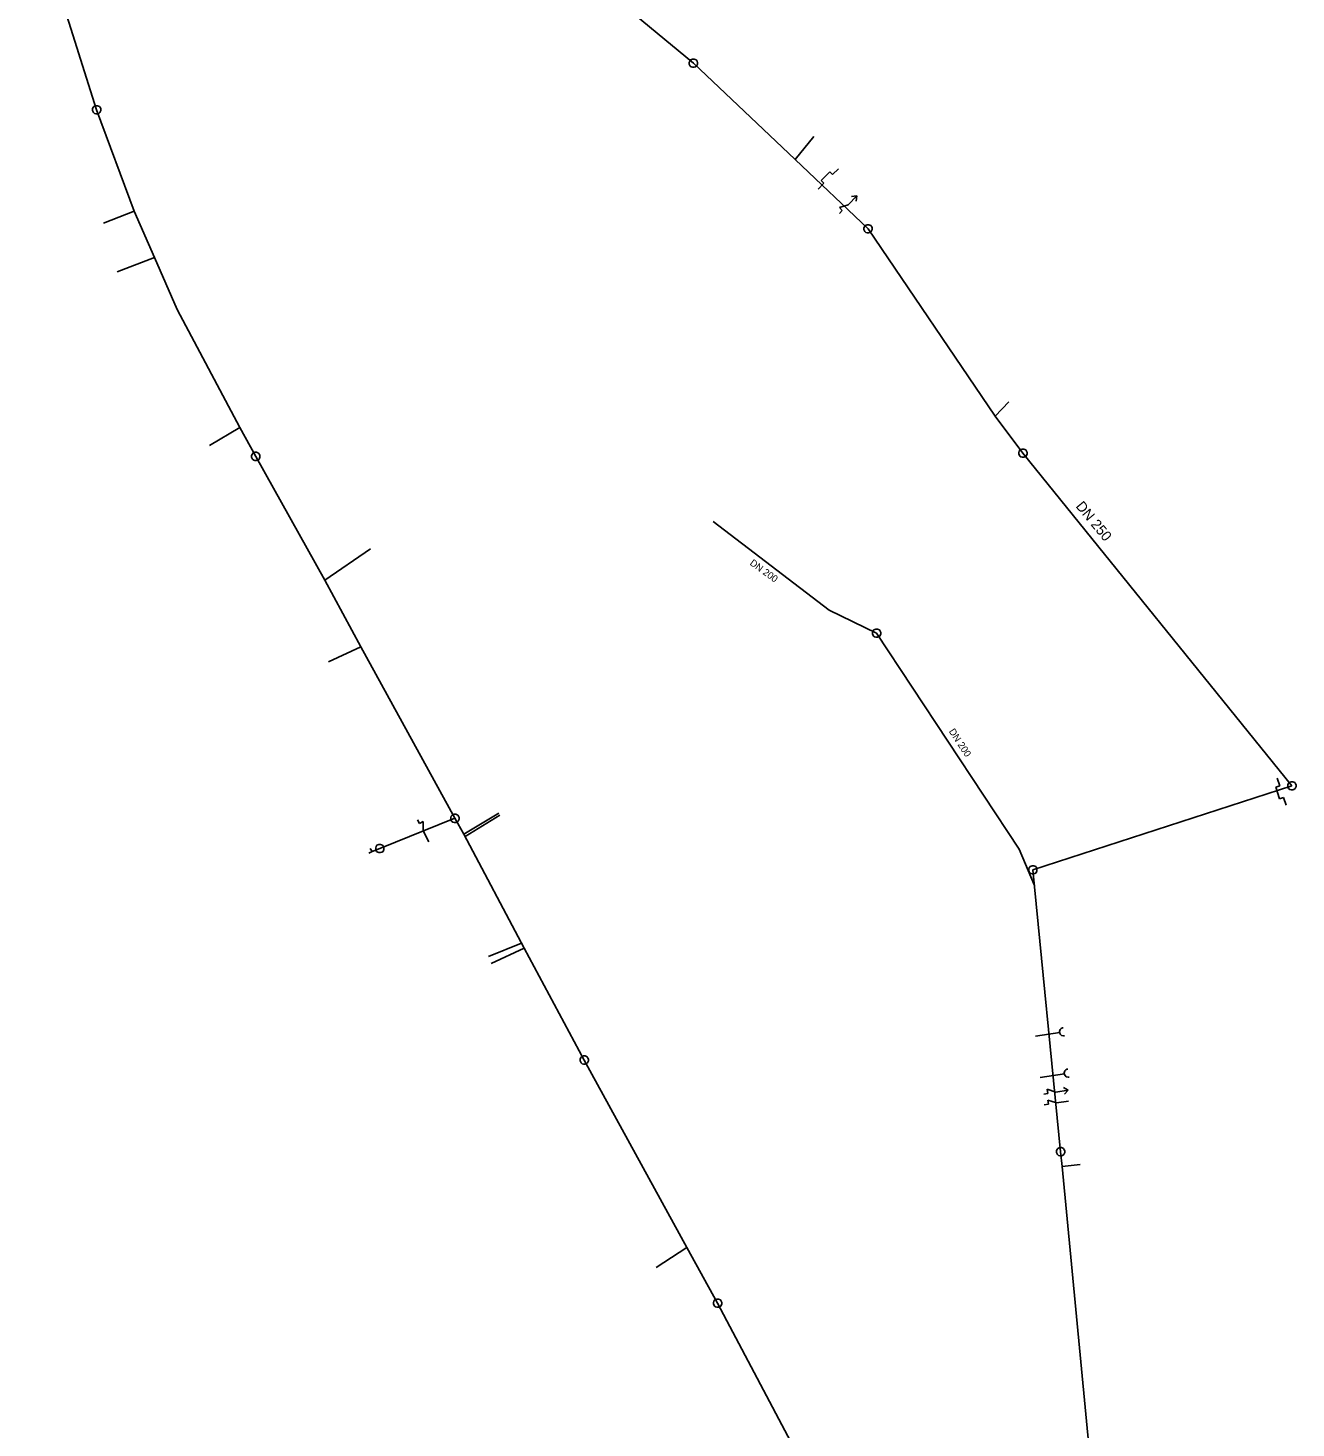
# Model space of a CAD drawing. Extents: x -717256 to -716843, y -1145423 to -1142840.
# Drawn here: x -717124.6 to -716969.5, y -1144562.5 to -1144391.3 of the extents above; entities that cross this region are included whole.
import ezdxf

# ---------------------------------------------------------------- set-up
doc = ezdxf.new("R2010")
doc.units = 0
for name, color, linetype in [('Vrstva 30', 7, 'Continuous'), ('Vrstva 31', 7, 'Continuous'), ('Vrstva 9', 7, 'Continuous')]:
    doc.layers.add(name, color=color, linetype=linetype)

msp = doc.modelspace()

# ---------------------------------------------------------------- linework, layer by layer
at = {"layer": 'Vrstva 30'}
for p, q in [((-717116.213, -1144401.308), (-717124.609, -1144374.682)), ((-717055.56, -1144385.37), (-717043.24, -1144395.61)), ((-717043.74, -1144395.51), (-717043.69, -1144395.36)), ((-717043.74, -1144395.71), (-717043.74, -1144395.51)), ((-717043.64, -1144395.96), (-717043.74, -1144395.71)), ((-717043.69, -1144395.36), (-717043.59, -1144395.21)), ((-717043.49, -1144396.06), (-717043.64, -1144395.96)), ((-717043.59, -1144395.21), (-717043.34, -1144395.11)), ((-717043.34, -1144396.11), (-717043.49, -1144396.06)), ((-717043.34, -1144395.11), (-717043.14, -1144395.11)), ((-717043.14, -1144396.11), (-717043.34, -1144396.11)), ((-717043.24, -1144395.61), (-717030.8, -1144407.402)), ((-717043.14, -1144395.11), (-717042.89, -1144395.21)), ((-717042.99, -1144396.06), (-717043.14, -1144396.11)), ((-717042.84, -1144395.96), (-717042.99, -1144396.06)), ((-717042.89, -1144395.21), (-717042.79, -1144395.36)), ((-717042.74, -1144395.71), (-717042.84, -1144395.96)), ((-717042.79, -1144395.36), (-717042.74, -1144395.51)), ((-717042.74, -1144395.51), (-717042.74, -1144395.71)), ((-717116.713, -1144401.208), (-717116.663, -1144401.058)), ((-717116.713, -1144401.408), (-717116.713, -1144401.208)), ((-717116.663, -1144401.058), (-717116.563, -1144400.908)), ((-717116.563, -1144400.908), (-717116.313, -1144400.808)), ((-717116.313, -1144400.808), (-717116.113, -1144400.808)), ((-717111.636, -1144413.702), (-717116.213, -1144401.308)), ((-717116.113, -1144400.808), (-717115.863, -1144400.908)), ((-717115.863, -1144400.908), (-717115.763, -1144401.058)), ((-717115.763, -1144401.058), (-717115.713, -1144401.208)), ((-717115.713, -1144401.208), (-717115.713, -1144401.408)), ((-717116.613, -1144401.658), (-717116.713, -1144401.408)), ((-717116.463, -1144401.758), (-717116.613, -1144401.658)), ((-717116.313, -1144401.808), (-717116.463, -1144401.758)), ((-717116.113, -1144401.808), (-717116.313, -1144401.808)), ((-717115.963, -1144401.758), (-717116.113, -1144401.808)), ((-717115.813, -1144401.658), (-717115.963, -1144401.758)), ((-717115.713, -1144401.408), (-717115.813, -1144401.658)), ((-717030.8, -1144407.402), (-717021.88, -1144415.86)), ((-717109.14, -1144419.386), (-717111.636, -1144413.702)), ((-717022.38, -1144415.76), (-717022.33, -1144415.61)), ((-717022.38, -1144415.96), (-717022.38, -1144415.76)), ((-717022.28, -1144416.21), (-717022.38, -1144415.96)), ((-717022.33, -1144415.61), (-717022.23, -1144415.46)), ((-717022.13, -1144416.31), (-717022.28, -1144416.21)), ((-717022.23, -1144415.46), (-717021.98, -1144415.36)), ((-717021.98, -1144416.36), (-717022.13, -1144416.31)), ((-717021.98, -1144415.36), (-717021.78, -1144415.36)), ((-717021.78, -1144416.36), (-717021.98, -1144416.36)), ((-717021.88, -1144415.86), (-717006.35, -1144438.77)), ((-717021.78, -1144415.36), (-717021.53, -1144415.46)), ((-717021.63, -1144416.31), (-717021.78, -1144416.36)), ((-717021.48, -1144416.21), (-717021.63, -1144416.31)), ((-717021.53, -1144415.46), (-717021.43, -1144415.61)), ((-717021.38, -1144415.96), (-717021.48, -1144416.21)), ((-717021.43, -1144415.61), (-717021.38, -1144415.76)), ((-717021.38, -1144415.76), (-717021.38, -1144415.96)), ((-717106.347, -1144425.727), (-717109.14, -1144419.386)), ((-717098.715, -1144440.159), (-717106.347, -1144425.727)), ((-717006.35, -1144438.77), (-717002.935, -1144443.298)), ((-717096.757, -1144443.693), (-717098.715, -1144440.159)), ((-717097.257, -1144443.593), (-717097.207, -1144443.443)), ((-717097.257, -1144443.793), (-717097.257, -1144443.593)), ((-717097.157, -1144444.043), (-717097.257, -1144443.793)), ((-717097.207, -1144443.443), (-717097.107, -1144443.293)), ((-717097.007, -1144444.143), (-717097.157, -1144444.043)), ((-717097.107, -1144443.293), (-717096.857, -1144443.193)), ((-717096.857, -1144443.193), (-717096.657, -1144443.193)), ((-717088.292, -1144458.816), (-717096.757, -1144443.693)), ((-717096.657, -1144443.193), (-717096.407, -1144443.293)), ((-717096.357, -1144444.043), (-717096.507, -1144444.143)), ((-717096.407, -1144443.293), (-717096.307, -1144443.443)), ((-717096.257, -1144443.793), (-717096.357, -1144444.043)), ((-717096.307, -1144443.443), (-717096.257, -1144443.593)), ((-717096.257, -1144443.593), (-717096.257, -1144443.793)), ((-717003.435, -1144443.198), (-717003.385, -1144443.048)), ((-717003.435, -1144443.398), (-717003.435, -1144443.198)), ((-717003.335, -1144443.648), (-717003.435, -1144443.398)), ((-717003.385, -1144443.048), (-717003.285, -1144442.898)), ((-717003.185, -1144443.748), (-717003.335, -1144443.648)), ((-717003.285, -1144442.898), (-717003.035, -1144442.798)), ((-717003.035, -1144443.798), (-717003.185, -1144443.748)), ((-717003.035, -1144442.798), (-717002.835, -1144442.798)), ((-717002.835, -1144443.798), (-717003.035, -1144443.798)), ((-717002.935, -1144443.298), (-716970.042, -1144483.973)), ((-717002.835, -1144442.798), (-717002.585, -1144442.898)), ((-717002.685, -1144443.748), (-717002.835, -1144443.798)), ((-717002.535, -1144443.648), (-717002.685, -1144443.748)), ((-717002.585, -1144442.898), (-717002.485, -1144443.048)), ((-717002.435, -1144443.398), (-717002.535, -1144443.648)), ((-717002.485, -1144443.048), (-717002.435, -1144443.198)), ((-717002.435, -1144443.198), (-717002.435, -1144443.398)), ((-717096.857, -1144444.193), (-717097.007, -1144444.143)), ((-717096.657, -1144444.193), (-717096.857, -1144444.193)), ((-717096.507, -1144444.143), (-717096.657, -1144444.193)), ((-717083.895, -1144466.986), (-717088.292, -1144458.816)), ((-717021.33, -1144465.21), (-717021.28, -1144465.06)), ((-717021.33, -1144465.41), (-717021.33, -1144465.21)), ((-717021.23, -1144465.66), (-717021.33, -1144465.41)), ((-717021.28, -1144465.06), (-717021.18, -1144464.91)), ((-717021.08, -1144465.76), (-717021.23, -1144465.66)), ((-717021.18, -1144464.91), (-717020.93, -1144464.81)), ((-717020.93, -1144465.81), (-717021.08, -1144465.76)), ((-717020.93, -1144464.81), (-717020.73, -1144464.81)), ((-717020.73, -1144465.81), (-717020.93, -1144465.81)), ((-717003.389, -1144491.727), (-717020.83, -1144465.31)), ((-717020.73, -1144464.81), (-717020.48, -1144464.91)), ((-717020.58, -1144465.76), (-717020.73, -1144465.81)), ((-717020.43, -1144465.66), (-717020.58, -1144465.76)), ((-717020.48, -1144464.91), (-717020.38, -1144465.06)), ((-717020.33, -1144465.41), (-717020.43, -1144465.66)), ((-717020.38, -1144465.06), (-717020.33, -1144465.21)), ((-717020.33, -1144465.21), (-717020.33, -1144465.41)), ((-717072.4, -1144487.954), (-717083.895, -1144466.986)), ((-716970.392, -1144483.573), (-716970.142, -1144483.473)), ((-716970.142, -1144483.473), (-716969.942, -1144483.473)), ((-716969.942, -1144483.473), (-716969.692, -1144483.573)), ((-717001.716, -1144494.256), (-716970.042, -1144483.973)), ((-716970.542, -1144483.873), (-716970.492, -1144483.723)), ((-716970.542, -1144484.073), (-716970.542, -1144483.873)), ((-716970.442, -1144484.323), (-716970.542, -1144484.073)), ((-716970.492, -1144483.723), (-716970.392, -1144483.573)), ((-716970.292, -1144484.423), (-716970.442, -1144484.323)), ((-716970.142, -1144484.473), (-716970.292, -1144484.423)), ((-716969.942, -1144484.473), (-716970.142, -1144484.473)), ((-716969.792, -1144484.423), (-716969.942, -1144484.473)), ((-716969.642, -1144484.323), (-716969.792, -1144484.423)), ((-716969.692, -1144483.573), (-716969.592, -1144483.723)), ((-716969.542, -1144484.073), (-716969.642, -1144484.323)), ((-716969.592, -1144483.723), (-716969.542, -1144483.873)), ((-716969.542, -1144483.873), (-716969.542, -1144484.073)), ((-717072.4, -1144487.954), (-717081.59, -1144491.65)), ((-717072.9, -1144487.854), (-717072.85, -1144487.704)), ((-717072.9, -1144488.054), (-717072.9, -1144487.854)), ((-717072.8, -1144488.304), (-717072.9, -1144488.054)), ((-717072.85, -1144487.704), (-717072.75, -1144487.554)), ((-717072.65, -1144488.404), (-717072.8, -1144488.304)), ((-717072.75, -1144487.554), (-717072.5, -1144487.454)), ((-717072.5, -1144488.454), (-717072.65, -1144488.404)), ((-717072.5, -1144487.454), (-717072.3, -1144487.454)), ((-717072.3, -1144488.454), (-717072.5, -1144488.454)), ((-717071.315, -1144489.899), (-717072.4, -1144487.954)), ((-717072.3, -1144487.454), (-717072.05, -1144487.554)), ((-717072.15, -1144488.404), (-717072.3, -1144488.454)), ((-717072, -1144488.304), (-717072.15, -1144488.404)), ((-717072.05, -1144487.554), (-717071.95, -1144487.704)), ((-717071.9, -1144488.054), (-717072, -1144488.304)), ((-717071.95, -1144487.704), (-717071.9, -1144487.854)), ((-717071.9, -1144487.854), (-717071.9, -1144488.054)), ((-717063.944, -1144503.812), (-717071.315, -1144489.899)), ((-717082.09, -1144491.55), (-717082.04, -1144491.4)), ((-717082.09, -1144491.75), (-717082.09, -1144491.55)), ((-717081.99, -1144492), (-717082.09, -1144491.75)), ((-717082.04, -1144491.4), (-717081.94, -1144491.25)), ((-717081.84, -1144492.1), (-717081.99, -1144492)), ((-717081.94, -1144491.25), (-717081.69, -1144491.15)), ((-717081.69, -1144491.15), (-717081.49, -1144491.15)), ((-717081.49, -1144491.15), (-717081.24, -1144491.25)), ((-717081.19, -1144492), (-717081.34, -1144492.1)), ((-717081.24, -1144491.25), (-717081.14, -1144491.4)), ((-717081.09, -1144491.75), (-717081.19, -1144492)), ((-717081.14, -1144491.4), (-717081.09, -1144491.55)), ((-717081.09, -1144491.55), (-717081.09, -1144491.75)), ((-717001.527, -1144496.17), (-717003.389, -1144491.727)), ((-717081.69, -1144492.15), (-717081.84, -1144492.1)), ((-717081.49, -1144492.15), (-717081.69, -1144492.15)), ((-717081.34, -1144492.1), (-717081.49, -1144492.15)), ((-717002.066, -1144493.856), (-717001.816, -1144493.756)), ((-717001.816, -1144493.756), (-717001.616, -1144493.756)), ((-717001.616, -1144493.756), (-717001.366, -1144493.856)), ((-717002.216, -1144494.156), (-717002.166, -1144494.006)), ((-717002.216, -1144494.356), (-717002.216, -1144494.156)), ((-717002.116, -1144494.606), (-717002.216, -1144494.356)), ((-717002.166, -1144494.006), (-717002.066, -1144493.856)), ((-717001.966, -1144494.706), (-717002.116, -1144494.606)), ((-717001.816, -1144494.756), (-717001.966, -1144494.706)), ((-717001.616, -1144494.756), (-717001.816, -1144494.756)), ((-717001.716, -1144494.256), (-716998.328, -1144528.729)), ((-717001.466, -1144494.706), (-717001.616, -1144494.756)), ((-717001.316, -1144494.606), (-717001.466, -1144494.706)), ((-717001.366, -1144493.856), (-717001.266, -1144494.006)), ((-717001.216, -1144494.356), (-717001.316, -1144494.606)), ((-717001.266, -1144494.006), (-717001.216, -1144494.156)), ((-717001.216, -1144494.156), (-717001.216, -1144494.356)), ((-717056.577, -1144517.515), (-717063.944, -1144503.812)), ((-717057.077, -1144517.415), (-717057.027, -1144517.265)), ((-717057.077, -1144517.615), (-717057.077, -1144517.415)), ((-717056.977, -1144517.865), (-717057.077, -1144517.615)), ((-717057.027, -1144517.265), (-717056.927, -1144517.115)), ((-717056.927, -1144517.115), (-717056.677, -1144517.015)), ((-717056.677, -1144517.015), (-717056.477, -1144517.015)), ((-717044.019, -1144540.452), (-717056.577, -1144517.515)), ((-717056.477, -1144517.015), (-717056.227, -1144517.115)), ((-717056.227, -1144517.115), (-717056.127, -1144517.265)), ((-717056.077, -1144517.615), (-717056.177, -1144517.865)), ((-717056.127, -1144517.265), (-717056.077, -1144517.415)), ((-717056.077, -1144517.415), (-717056.077, -1144517.615)), ((-717056.827, -1144517.965), (-717056.977, -1144517.865)), ((-717056.677, -1144518.015), (-717056.827, -1144517.965)), ((-717056.477, -1144518.015), (-717056.677, -1144518.015)), ((-717056.327, -1144517.965), (-717056.477, -1144518.015)), ((-717056.177, -1144517.865), (-717056.327, -1144517.965)), ((-716998.828, -1144528.629), (-716998.778, -1144528.479)), ((-716998.828, -1144528.829), (-716998.828, -1144528.629)), ((-716998.728, -1144529.079), (-716998.828, -1144528.829)), ((-716998.778, -1144528.479), (-716998.678, -1144528.329)), ((-716998.578, -1144529.179), (-716998.728, -1144529.079)), ((-716998.678, -1144528.329), (-716998.428, -1144528.229)), ((-716998.428, -1144529.229), (-716998.578, -1144529.179)), ((-716998.428, -1144528.229), (-716998.228, -1144528.229)), ((-716998.228, -1144529.229), (-716998.428, -1144529.229)), ((-716998.328, -1144528.729), (-716998.155, -1144530.526)), ((-716998.228, -1144528.229), (-716997.978, -1144528.329)), ((-716998.078, -1144529.179), (-716998.228, -1144529.229)), ((-716997.928, -1144529.079), (-716998.078, -1144529.179)), ((-716997.978, -1144528.329), (-716997.878, -1144528.479)), ((-716997.828, -1144528.829), (-716997.928, -1144529.079)), ((-716997.878, -1144528.479), (-716997.828, -1144528.629)), ((-716997.828, -1144528.629), (-716997.828, -1144528.829)), ((-716998.155, -1144530.526), (-716994.12, -1144572.47)), ((-717040.274, -1144547.245), (-717044.019, -1144540.452)), ((-717040.724, -1144546.995), (-717040.624, -1144546.845)), ((-717040.624, -1144546.845), (-717040.374, -1144546.745)), ((-717040.374, -1144546.745), (-717040.174, -1144546.745)), ((-717040.174, -1144546.745), (-717039.924, -1144546.845)), ((-717039.924, -1144546.845), (-717039.824, -1144546.995)), ((-717040.774, -1144547.145), (-717040.724, -1144546.995)), ((-717040.774, -1144547.345), (-717040.774, -1144547.145)), ((-717040.674, -1144547.595), (-717040.774, -1144547.345)), ((-717040.524, -1144547.695), (-717040.674, -1144547.595)), ((-717040.374, -1144547.745), (-717040.524, -1144547.695)), ((-717040.174, -1144547.745), (-717040.374, -1144547.745)), ((-717029.258, -1144568.056), (-717040.274, -1144547.245)), ((-717040.024, -1144547.695), (-717040.174, -1144547.745)), ((-717039.874, -1144547.595), (-717040.024, -1144547.695)), ((-717039.774, -1144547.345), (-717039.874, -1144547.595)), ((-717039.824, -1144546.995), (-717039.774, -1144547.145)), ((-717039.774, -1144547.145), (-717039.774, -1144547.345))]:
    msp.add_line(p, q, dxfattribs=at)
at = {"layer": 'Vrstva 31'}
for p, q in [((-717028.5, -1144404.56), (-717030.8, -1144407.402)), ((-717111.636, -1144413.702), (-717115.382, -1144415.153)), ((-717109.14, -1144419.386), (-717113.701, -1144421.142)), ((-717004.66, -1144437.02), (-717006.35, -1144438.77)), ((-717098.715, -1144440.159), (-717102.427, -1144442.374)), ((-717026.614, -1144462.488), (-717040.798, -1144451.641)), ((-717088.292, -1144458.816), (-717082.713, -1144454.998)), ((-717020.83, -1144465.31), (-717026.614, -1144462.488)), ((-717083.895, -1144466.986), (-717087.857, -1144468.821)), ((-717071.315, -1144489.899), (-717067.041, -1144487.305)), ((-717071.158, -1144490.194), (-717066.887, -1144487.584)), ((-717082.5, -1144492.03), (-717082.92, -1144492.21)), ((-717082.5, -1144492.03), (-717082.78, -1144491.66)), ((-717081.59, -1144491.65), (-717082.5, -1144492.03)), ((-717003.389, -1144491.727), (-717001.527, -1144496.17)), ((-717064.25, -1144503.233), (-717068.301, -1144504.848)), ((-717063.944, -1144503.812), (-717067.958, -1144505.7)), ((-716998.155, -1144530.526), (-716995.94, -1144530.275)), ((-717044.019, -1144540.452), (-717047.785, -1144542.881))]:
    msp.add_line(p, q, dxfattribs=at)
at = {"layer": 'Vrstva 9'}
for p, q in [((-717026.563, -1144408.876), (-717027.623, -1144409.936)), ((-717026.209, -1144409.229), (-717026.563, -1144408.876)), ((-717025.502, -1144408.522), (-717026.209, -1144409.229)), ((-717027.27, -1144410.29), (-717027.977, -1144410.997)), ((-717027.623, -1144409.936), (-717027.27, -1144410.29)), ((-717025.38, -1144413.263), (-717024.32, -1144412.91)), ((-717025.027, -1144413.617), (-717025.38, -1144413.263)), ((-717024.32, -1144412.91), (-717023.259, -1144411.849)), ((-717023.895, -1144411.92), (-717023.259, -1144411.849)), ((-717023.259, -1144411.849), (-717023.33, -1144412.485)), ((-717025.38, -1144413.97), (-717025.027, -1144413.617)), ((-716971.844, -1144483.024), (-716971.535, -1144483.975)), ((-716971.535, -1144483.975), (-716972.011, -1144484.13)), ((-716972.011, -1144484.13), (-716971.547, -1144485.556)), ((-716971.547, -1144485.556), (-716971.072, -1144485.402)), ((-716971.072, -1144485.402), (-716970.763, -1144486.353)), ((-717076.96, -1144488.143), (-717076.734, -1144488.589)), ((-717076.734, -1144488.589), (-717076.288, -1144488.362)), ((-717076.288, -1144488.362), (-717076.28, -1144489.48)), ((-717076.28, -1144489.48), (-717075.599, -1144490.816)), ((-716998.431, -1144514.14), (-717001.394, -1144514.609)), ((-716998.447, -1144514.041), (-716998.387, -1144513.779)), ((-716998.415, -1144514.239), (-716998.447, -1144514.041)), ((-716998.342, -1144514.379), (-716998.415, -1144514.239)), ((-716998.387, -1144513.779), (-716998.254, -1144513.656)), ((-716998.254, -1144513.656), (-716998.114, -1144513.584)), ((-716998.114, -1144513.584), (-716998.015, -1144513.568)), ((-716998.22, -1144514.512), (-716998.342, -1144514.379)), ((-716997.958, -1144514.571), (-716998.22, -1144514.512)), ((-716997.859, -1144514.556), (-716997.958, -1144514.571)), ((-716997.866, -1144519.185), (-717000.829, -1144519.654)), ((-716997.882, -1144519.086), (-716997.822, -1144518.824)), ((-716997.85, -1144519.284), (-716997.882, -1144519.086)), ((-716997.777, -1144519.424), (-716997.85, -1144519.284)), ((-716997.822, -1144518.824), (-716997.689, -1144518.701)), ((-716997.655, -1144519.557), (-716997.777, -1144519.424)), ((-716997.689, -1144518.701), (-716997.549, -1144518.629)), ((-716997.549, -1144518.629), (-716997.45, -1144518.613)), ((-716999.887, -1144521.589), (-716999.965, -1144521.095)), ((-716999.965, -1144521.095), (-716998.9, -1144521.433)), ((-716997.974, -1144520.881), (-716997.418, -1144521.198)), ((-716997.393, -1144519.616), (-716997.655, -1144519.557)), ((-716997.294, -1144519.601), (-716997.393, -1144519.616)), ((-717000.381, -1144521.667), (-716999.887, -1144521.589)), ((-716999.828, -1144522.916), (-716999.906, -1144522.422)), ((-716999.906, -1144522.422), (-716998.841, -1144522.76)), ((-716998.9, -1144521.433), (-716997.418, -1144521.198)), ((-716998.841, -1144522.76), (-716997.359, -1144522.525)), ((-716997.418, -1144521.198), (-716997.849, -1144521.671)), ((-717000.322, -1144522.994), (-716999.828, -1144522.916))]:
    msp.add_line(p, q, dxfattribs=at)

# ---------------------------------------------------------------- texts
at = {"layer": 'Vrstva 30'}
for s, height, rotation, p in [('DN 250', 1.25, 309.6, (-716996.544, -1144449.819)), ('DN 200', 0.85, 303.3, (-717012.033, -1144477.32))]:
    msp.add_text(s, height=height, rotation=rotation, dxfattribs=at).set_placement(p)
at = {"layer": 'Vrstva 31'}
msp.add_text('DN 200', height=0.85, rotation=324, dxfattribs=at).set_placement((-717036.413, -1144456.889))

doc.saveas('drawing.dxf')
